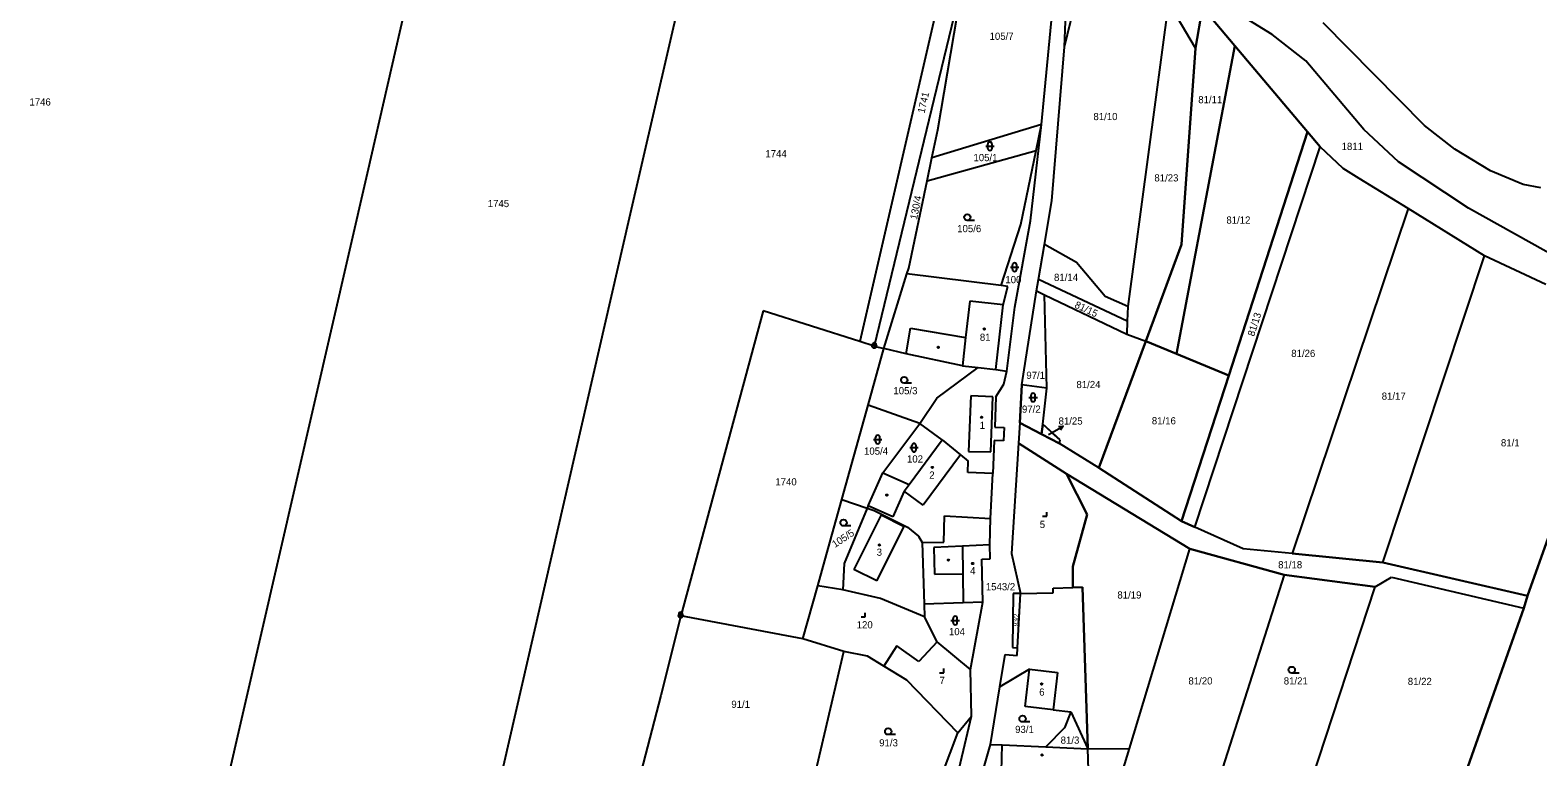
# Model space of a CAD drawing. Extents: x -801826 to -800592, y -1032871 to -1031813.
# Drawn here: x -801815 to -801458.2, y -1032222.7 to -1032050.6 of the extents above; entities that cross this region are included whole.
import ezdxf

# ---------------------------------------------------------------- set-up
doc = ezdxf.new("R2010")
doc.units = 0
for name, color, linetype in [('Vrstva 1', 7, 'Continuous'), ('Vrstva 16', 7, 'Continuous'), ('Vrstva 18', 7, 'Continuous'), ('Vrstva 19', 7, 'Continuous'), ('Vrstva 24', 7, 'Continuous'), ('Vrstva 25', 7, 'Continuous'), ('Vrstva 4', 7, 'Continuous')]:
    doc.layers.add(name, color=color, linetype=linetype)

msp = doc.modelspace()

# ---------------------------------------------------------------- linework, layer by layer
at = {"layer": 'Vrstva 1'}
for p, q in [((-801696.39, -1031915.49), (-801735.27, -1032084.52)), ((-801635.15, -1031929.7), (-801673.2, -1032095.09)), ((-801592.85, -1032012.2), (-801618.6, -1032124.34)), ((-801570.22, -1032054.57), (-801564.72, -1032031.99)), ((-801593.88, -1032036.96), (-801615.22, -1032125.41)), ((-801600.19, -1032074.16), (-801593.88, -1032036.96)), ((-801575.66, -1032072.95), (-801571.93, -1032034.16)), ((-801570.22, -1032054.57), (-801569.48, -1032037.37)), ((-801545.6, -1032044.06), (-801555.21, -1032116.05)), ((-801539.15, -1032054.89), (-801545.6, -1032044.06)), ((-801539.15, -1032054.89), (-801537.52, -1032045.21)), ((-801537.52, -1032045.21), (-801539.15, -1032054.89)), ((-801537.52, -1032045.21), (-801529.87, -1032054.28)), ((-801529.87, -1032054.28), (-801537.52, -1032045.21)), ((-801521.04, -1032051.65), (-801529.66, -1032046.3)), ((-801484.98, -1032073.21), (-801508.93, -1032048.86)), ((-801573.2, -1032091.04), (-801570.22, -1032054.57)), ((-801543.66, -1032127.26), (-801529.87, -1032054.28)), ((-801543.66, -1032127.26), (-801529.87, -1032054.28)), ((-801529.87, -1032054.28), (-801543.66, -1032127.26)), ((-801542.47, -1032101.33), (-801539.15, -1032054.89)), ((-801539.15, -1032054.89), (-801542.47, -1032101.33)), ((-801529.87, -1032054.28), (-801512.68, -1032074.66)), ((-801512.68, -1032074.66), (-801529.87, -1032054.28)), ((-801513.04, -1032057.88), (-801521.04, -1032051.65)), ((-801499.37, -1032074.08), (-801513.04, -1032057.88)), ((-801575.66, -1032072.95), (-801601.58, -1032080.79)), ((-801601.58, -1032080.79), (-801600.19, -1032074.16)), ((-801578.22, -1032095.71), (-801575.66, -1032072.95)), ((-801576.93, -1032079.13), (-801575.66, -1032072.95)), ((-801531.32, -1032132.37), (-801512.68, -1032074.66)), ((-801531.32, -1032132.37), (-801512.68, -1032074.66)), ((-801512.68, -1032074.66), (-801531.32, -1032132.37)), ((-801512.68, -1032074.66), (-801509.66, -1032078.24)), ((-801509.66, -1032078.24), (-801512.68, -1032074.66)), ((-801491.14, -1032081.75), (-801499.37, -1032074.08)), ((-801477.81, -1032078.75), (-801484.98, -1032073.21)), ((-801602.73, -1032086.28), (-801576.93, -1032079.13)), ((-801580.52, -1032096.58), (-801576.93, -1032079.13)), ((-801539.33, -1032168.25), (-801509.66, -1032078.24)), ((-801539.33, -1032168.25), (-801509.66, -1032078.24)), ((-801504.27, -1032083.33), (-801509.66, -1032078.24)), ((-801469.34, -1032083.91), (-801477.81, -1032078.75)), ((-801602.73, -1032086.28), (-801601.58, -1032080.79)), ((-801500.48, -1032085.74), (-801504.27, -1032083.33)), ((-801474.57, -1032092.78), (-801491.14, -1032081.75)), ((-801735.27, -1032084.52), (-801774.16, -1032253.56)), ((-801607.05, -1032106.95), (-801602.73, -1032086.28)), ((-801488.81, -1032092.82), (-801500.48, -1032085.74)), ((-801461.63, -1032087.11), (-801469.34, -1032083.91)), ((-801457.47, -1032087.94), (-801461.63, -1032087.11)), ((-801574.95, -1032101.34), (-801573.2, -1032091.04)), ((-801488.81, -1032092.82), (-801516.29, -1032174.51)), ((-801488.81, -1032092.82), (-801516.29, -1032174.51)), ((-801470.82, -1032104.06), (-801488.81, -1032092.82)), ((-801470.82, -1032104.06), (-801488.81, -1032092.82)), ((-801452.83, -1032104.89), (-801474.57, -1032092.78)), ((-801673.2, -1032095.09), (-801711.24, -1032260.47)), ((-801585.14, -1032111.09), (-801580.52, -1032096.58)), ((-801581.96, -1032116.17), (-801578.22, -1032095.71)), ((-801576.36, -1032109.6), (-801574.95, -1032101.34)), ((-801567.33, -1032105.58), (-801574.95, -1032101.34)), ((-801550.96, -1032124.23), (-801542.47, -1032101.33)), ((-801542.47, -1032101.33), (-801550.96, -1032124.23)), ((-801494.86, -1032176.63), (-801470.82, -1032104.06)), ((-801494.86, -1032176.63), (-801470.82, -1032104.06)), ((-801456.3, -1032110.81), (-801470.82, -1032104.06)), ((-801612.91, -1032125.95), (-801607.47, -1032108.32)), ((-801607.47, -1032108.32), (-801607.05, -1032106.95)), ((-801585.14, -1032111.09), (-801607.47, -1032108.32)), ((-801560.57, -1032113.65), (-801567.33, -1032105.58)), ((-801583.58, -1032111.28), (-801585.14, -1032111.09)), ((-801584.71, -1032115.66), (-801583.58, -1032111.28)), ((-801576.83, -1032112.35), (-801576.36, -1032109.6)), ((-801555.35, -1032119.53), (-801576.36, -1032109.6)), ((-801580.28, -1032134.57), (-801576.83, -1032112.35)), ((-801576.83, -1032112.35), (-801574.91, -1032113.27)), ((-801574.91, -1032113.27), (-801555.47, -1032122.58)), ((-801574.33, -1032135.39), (-801574.91, -1032113.27)), ((-801555.21, -1032116.05), (-801560.57, -1032113.65)), ((-801641.49, -1032117.07), (-801661.01, -1032189.25)), ((-801618.6, -1032124.34), (-801641.49, -1032117.07)), ((-801586.44, -1032130.95), (-801584.71, -1032115.66)), ((-801583.86, -1032131.32), (-801581.96, -1032116.17)), ((-801555.21, -1032116.05), (-801555.35, -1032119.53)), ((-801555.35, -1032119.53), (-801555.47, -1032122.58)), ((-801555.47, -1032122.58), (-801550.96, -1032124.23)), ((-801460.58, -1032184.52), (-801438.33, -1032121.65)), ((-801438.33, -1032121.65), (-801460.58, -1032184.52)), ((-801615.22, -1032125.41), (-801618.6, -1032124.34)), ((-801616.66, -1032139.4), (-801612.91, -1032125.95)), ((-801615.22, -1032125.41), (-801612.91, -1032125.95)), ((-801607.7, -1032127.27), (-801612.91, -1032125.95)), ((-801562.08, -1032154.26), (-801550.96, -1032124.23)), ((-801550.96, -1032124.23), (-801562.08, -1032154.26)), ((-801550.96, -1032124.23), (-801543.66, -1032127.26)), ((-801550.96, -1032124.23), (-801543.66, -1032127.26)), ((-801543.66, -1032127.26), (-801550.96, -1032124.23)), ((-801594.34, -1032130.06), (-801607.7, -1032127.27)), ((-801543.66, -1032127.26), (-801531.32, -1032132.37)), ((-801543.66, -1032127.26), (-801531.32, -1032132.37)), ((-801531.32, -1032132.37), (-801543.66, -1032127.26)), ((-801600.42, -1032137.74), (-801590.61, -1032130.48)), ((-801594.34, -1032130.06), (-801590.61, -1032130.48)), ((-801590.61, -1032130.48), (-801586.44, -1032130.95)), ((-801586.44, -1032130.95), (-801583.86, -1032131.32)), ((-801584.52, -1032134.38), (-801583.86, -1032131.32)), ((-801542.47, -1032166.88), (-801531.32, -1032132.37)), ((-801531.32, -1032132.37), (-801542.47, -1032166.88)), ((-801542.47, -1032166.88), (-801531.32, -1032132.37)), ((-801586.42, -1032137.42), (-801584.52, -1032134.38)), ((-801580.75, -1032143.57), (-801580.28, -1032134.57)), ((-801580.28, -1032134.57), (-801580.75, -1032143.57)), ((-801574.33, -1032135.39), (-801580.28, -1032134.57)), ((-801574.33, -1032135.39), (-801580.28, -1032134.57)), ((-801575.35, -1032143.86), (-801574.33, -1032135.39)), ((-801575.35, -1032143.86), (-801574.33, -1032135.39)), ((-801622.88, -1032161.7), (-801616.66, -1032139.4)), ((-801604.39, -1032143.72), (-801616.66, -1032139.4)), ((-801604.39, -1032143.72), (-801600.42, -1032137.74)), ((-801586.42, -1032137.42), (-801586.7, -1032144.58)), ((-801613.16, -1032155.4), (-801604.39, -1032143.72)), ((-801599.15, -1032147.62), (-801604.39, -1032143.72)), ((-801580.75, -1032143.57), (-801581.06, -1032148.37)), ((-801580.75, -1032143.57), (-801581.06, -1032148.37)), ((-801575.64, -1032146.25), (-801580.75, -1032143.57)), ((-801575.64, -1032146.25), (-801580.75, -1032143.57)), ((-801580.75, -1032143.57), (-801575.64, -1032146.25)), ((-801575.35, -1032143.86), (-801575.64, -1032146.25)), ((-801575.35, -1032143.86), (-801575.64, -1032146.25)), ((-801575.64, -1032146.25), (-801575.35, -1032143.86)), ((-801571.25, -1032147.62), (-801575.35, -1032143.86)), ((-801606.96, -1032158.17), (-801599.15, -1032147.62)), ((-801599.15, -1032147.62), (-801594.84, -1032151.14)), ((-801586.7, -1032144.58), (-801584.5, -1032144.66)), ((-801584.5, -1032144.66), (-801584.62, -1032147.83)), ((-801571.38, -1032148.48), (-801575.64, -1032146.25)), ((-801571.38, -1032148.48), (-801575.64, -1032146.25)), ((-801575.64, -1032146.25), (-801571.38, -1032148.48)), ((-801571.38, -1032148.48), (-801571.25, -1032147.62)), ((-801571.38, -1032148.48), (-801571.25, -1032147.62)), ((-801594.84, -1032151.14), (-801592.98, -1032152.66)), ((-801586.82, -1032147.74), (-801587.13, -1032155.6)), ((-801584.62, -1032147.83), (-801586.82, -1032147.74)), ((-801581.06, -1032148.37), (-801582.72, -1032174.51)), ((-801581.06, -1032148.37), (-801582.72, -1032174.51)), ((-801569.71, -1032155.65), (-801581.06, -1032148.37)), ((-801569.71, -1032155.65), (-801581.06, -1032148.37)), ((-801581.06, -1032148.37), (-801569.71, -1032155.65)), ((-801562.08, -1032154.26), (-801571.38, -1032148.48)), ((-801562.08, -1032154.26), (-801571.38, -1032148.48)), ((-801593.08, -1032155.37), (-801592.98, -1032152.66)), ((-801542.47, -1032166.88), (-801562.08, -1032154.26)), ((-801562.08, -1032154.26), (-801542.47, -1032166.88)), ((-801542.47, -1032166.88), (-801562.08, -1032154.26)), ((-801616.66, -1032163.25), (-801613.16, -1032155.4)), ((-801613.16, -1032155.4), (-801606.96, -1032158.17)), ((-801587.13, -1032155.6), (-801593.08, -1032155.37)), ((-801587.74, -1032166.2), (-801587.13, -1032155.6)), ((-801564.85, -1032165.28), (-801569.71, -1032155.65)), ((-801569.71, -1032155.65), (-801540.51, -1032173.41)), ((-801564.85, -1032165.28), (-801569.71, -1032155.65)), ((-801569.71, -1032155.65), (-801540.51, -1032173.41)), ((-801569.71, -1032155.65), (-801564.85, -1032165.28)), ((-801540.51, -1032173.41), (-801569.71, -1032155.65)), ((-801626.52, -1032174.73), (-801622.88, -1032161.7)), ((-801622.88, -1032161.7), (-801616.89, -1032163.75)), ((-801616.89, -1032163.75), (-801622.35, -1032176.9)), ((-801616.66, -1032163.25), (-801616.89, -1032163.75)), ((-801616.89, -1032163.75), (-801615.25, -1032164.31)), ((-801615.25, -1032164.31), (-801607.33, -1032168.28)), ((-801568.24, -1032177.58), (-801564.85, -1032165.28)), ((-801568.24, -1032177.58), (-801564.85, -1032165.28)), ((-801564.85, -1032165.28), (-801568.24, -1032177.58)), ((-801607.33, -1032168.28), (-801604.76, -1032170.44)), ((-801598.76, -1032171.83), (-801598.55, -1032165.58)), ((-801598.55, -1032165.58), (-801587.74, -1032166.2)), ((-801587.88, -1032172.45), (-801587.74, -1032166.2)), ((-801539.33, -1032168.25), (-801542.47, -1032166.88)), ((-801542.47, -1032166.88), (-801539.33, -1032168.25)), ((-801539.33, -1032168.25), (-801542.47, -1032166.88)), ((-801527.92, -1032173.38), (-801539.33, -1032168.25)), ((-801527.92, -1032173.38), (-801539.33, -1032168.25)), ((-801604.76, -1032170.44), (-801603.87, -1032171.87)), ((-801603.87, -1032171.87), (-801598.76, -1032171.83)), ((-801603.87, -1032171.87), (-801603.38, -1032186.52)), ((-801587.8, -1032175.74), (-801587.88, -1032172.45)), ((-801628.6, -1032182.17), (-801626.52, -1032174.73)), ((-801589.74, -1032175.82), (-801587.8, -1032175.74)), ((-801589.52, -1032186), (-801589.74, -1032175.82)), ((-801582.72, -1032174.51), (-801580.58, -1032183.95)), ((-801582.72, -1032174.51), (-801580.58, -1032183.95)), ((-801554.81, -1032220.67), (-801540.51, -1032173.41)), ((-801554.81, -1032220.67), (-801540.51, -1032173.41)), ((-801518.17, -1032179.53), (-801540.51, -1032173.41)), ((-801540.51, -1032173.41), (-801518.17, -1032179.53)), ((-801516.29, -1032174.51), (-801527.92, -1032173.38)), ((-801516.29, -1032174.51), (-801527.92, -1032173.38)), ((-801516.29, -1032174.51), (-801494.86, -1032176.63)), ((-801516.29, -1032174.51), (-801494.86, -1032176.63)), ((-801494.86, -1032176.63), (-801516.29, -1032174.51)), ((-801622.35, -1032176.9), (-801622.62, -1032183.14)), ((-801568.2, -1032182.56), (-801568.24, -1032177.58)), ((-801568.2, -1032182.56), (-801568.24, -1032177.58)), ((-801568.24, -1032177.58), (-801568.2, -1032182.56)), ((-801518.17, -1032179.53), (-801535.05, -1032232.41)), ((-801496.63, -1032182.4), (-801518.17, -1032179.53)), ((-801518.17, -1032179.53), (-801496.63, -1032182.4)), ((-801494.86, -1032176.63), (-801460.58, -1032184.52)), ((-801460.58, -1032184.52), (-801494.86, -1032176.63)), ((-801632.1, -1032194.71), (-801628.6, -1032182.17)), ((-801622.62, -1032183.14), (-801628.6, -1032182.17)), ((-801613.75, -1032185.19), (-801622.62, -1032183.14)), ((-801572.9, -1032182.72), (-801568.2, -1032182.56)), ((-801572.9, -1032182.72), (-801568.2, -1032182.56)), ((-801572.87, -1032183.8), (-801572.9, -1032182.72)), ((-801572.87, -1032183.8), (-801572.9, -1032182.72)), ((-801565.96, -1032182.51), (-801568.2, -1032182.56)), ((-801568.2, -1032182.56), (-801565.96, -1032182.51)), ((-801564.66, -1032220.77), (-801565.96, -1032182.51)), ((-801565.96, -1032182.51), (-801564.66, -1032220.77)), ((-801511.73, -1032228.35), (-801496.63, -1032182.4)), ((-801496.63, -1032182.4), (-801492.79, -1032180.13)), ((-801496.63, -1032182.4), (-801492.79, -1032180.13)), ((-801492.79, -1032180.13), (-801461.5, -1032187.46)), ((-801492.79, -1032180.13), (-801461.5, -1032187.46)), ((-801603.31, -1032189.54), (-801613.75, -1032185.19)), ((-801594.15, -1032186.18), (-801603.38, -1032186.52)), ((-801603.38, -1032186.52), (-801603.31, -1032189.54)), ((-801589.52, -1032186), (-801594.15, -1032186.18)), ((-801592.45, -1032201.97), (-801589.52, -1032186)), ((-801582.3, -1032183.98), (-801582.5, -1032196.8)), ((-801580.58, -1032183.95), (-801582.3, -1032183.98)), ((-801581.29, -1032196.85), (-801580.58, -1032183.95)), ((-801580.58, -1032183.95), (-801572.87, -1032183.8)), ((-801580.58, -1032183.95), (-801572.87, -1032183.8)), ((-801461.5, -1032187.46), (-801460.58, -1032184.52)), ((-801460.58, -1032184.52), (-801461.5, -1032187.46)), ((-801461.5, -1032187.46), (-801460.58, -1032184.52)), ((-801661.01, -1032189.25), (-801665.7, -1032208.11)), ((-801634.66, -1032194.23), (-801661.01, -1032189.25)), ((-801600.29, -1032195.45), (-801603.31, -1032189.54)), ((-801474.72, -1032225.02), (-801461.5, -1032187.46)), ((-801461.5, -1032187.46), (-801474.72, -1032225.02)), ((-801632.1, -1032194.71), (-801634.66, -1032194.23)), ((-801622.41, -1032197.71), (-801632.1, -1032194.71)), ((-801609.89, -1032196.36), (-801612.98, -1032201.16)), ((-801604.63, -1032200.11), (-801609.89, -1032196.36)), ((-801600.29, -1032195.45), (-801604.63, -1032200.11)), ((-801592.45, -1032201.97), (-801600.29, -1032195.45)), ((-801582.5, -1032196.8), (-801581.29, -1032196.85)), ((-801581.39, -1032198.64), (-801581.29, -1032196.85)), ((-801630.3, -1032231.27), (-801622.41, -1032197.71)), ((-801616.84, -1032198.81), (-801622.41, -1032197.71)), ((-801612.98, -1032201.16), (-801616.84, -1032198.81)), ((-801607.5, -1032204.51), (-801612.98, -1032201.16)), ((-801585.47, -1032206.05), (-801584.24, -1032198.44)), ((-801584.24, -1032198.44), (-801581.39, -1032198.64)), ((-801595.46, -1032216.99), (-801607.5, -1032204.51)), ((-801592.18, -1032213.05), (-801592.45, -1032201.97)), ((-801578.49, -1032201.93), (-801585.47, -1032206.05)), ((-801579.52, -1032210.71), (-801578.49, -1032201.93)), ((-801665.7, -1032208.11), (-801671.46, -1032230.29)), ((-801587.68, -1032219.71), (-801585.47, -1032206.05)), ((-801572.9, -1032211.49), (-801579.52, -1032210.71)), ((-801572.9, -1032211.49), (-801568.72, -1032211.97)), ((-801601.75, -1032253.31), (-801592.18, -1032213.05)), ((-801595.46, -1032216.99), (-801592.18, -1032213.05)), ((-801568.72, -1032211.97), (-801570.15, -1032215.77)), ((-801568.72, -1032211.97), (-801564.66, -1032220.77)), ((-801602.24, -1032235.1), (-801595.46, -1032216.99)), ((-801570.15, -1032215.77), (-801574.57, -1032220.31)), ((-801592.61, -1032236.62), (-801587.68, -1032219.71)), ((-801587.68, -1032219.71), (-801584.92, -1032219.84)), ((-801584.92, -1032219.84), (-801574.57, -1032220.31)), ((-801574.57, -1032220.31), (-801564.66, -1032220.77)), ((-801564.66, -1032220.77), (-801554.81, -1032220.67)), ((-801564.66, -1032220.77), (-801554.81, -1032220.67)), ((-801564.26, -1032232.36), (-801564.66, -1032220.77)), ((-801559.71, -1032236.89), (-801554.81, -1032220.67))]:
    msp.add_line(p, q, dxfattribs=at)
msp.add_lwpolyline([(-801571.25, -1032147.62), (-801573.17, -1032145.86), (-801575.35, -1032143.86)], dxfattribs=at)
at = {"layer": 'Vrstva 16'}
for p, q in [((-801573.96, -1032146.31), (-801573.13, -1032145.83)), ((-801573.13, -1032145.83), (-801570.52, -1032144.35))]:
    msp.add_line(p, q, dxfattribs=at)
msp.add_lwpolyline([(-801571.64, -1032144.41), (-801570.52, -1032144.35), (-801571.14, -1032145.28)], dxfattribs=at)
at = {"layer": 'Vrstva 24'}
for centre, radius in [((-801615.22, -1032125.41), 0.5), ((-801615.22, -1032125.41), 0.0364), ((-801661.01, -1032189.25), 0.5), ((-801661.01, -1032189.25), 0.0364)]:
    msp.add_circle(centre, radius, dxfattribs=at)
for centre in [(-801615.22, -1032125.04), (-801661.01, -1032188.88)]:
    msp.add_arc(centre, 0.45, 344.4473, 196.3778, dxfattribs=at)
at = {"layer": 'Vrstva 25'}
for p, q in [((-801588.84, -1032078.09), (-801586.84, -1032078.09)), ((-801588.34, -1032078.59), (-801588.34, -1032077.59)), ((-801587.34, -1032078.59), (-801587.34, -1032077.59)), ((-801591.45, -1032095.65), (-801593.2, -1032095.65)), ((-801583, -1032106.72), (-801581, -1032106.72)), ((-801582.5, -1032107.22), (-801582.5, -1032106.22)), ((-801581.5, -1032107.22), (-801581.5, -1032106.22)), ((-801606.37, -1032134.19), (-801608.12, -1032134.19)), ((-801578.61, -1032137.55), (-801576.61, -1032137.55)), ((-801578.11, -1032138.05), (-801578.11, -1032137.05)), ((-801577.11, -1032138.05), (-801577.11, -1032137.05)), ((-801615.39, -1032147.53), (-801613.39, -1032147.53)), ((-801614.89, -1032148.03), (-801614.89, -1032147.03)), ((-801613.89, -1032148.03), (-801613.89, -1032147.03)), ((-801606.81, -1032149.44), (-801604.81, -1032149.44)), ((-801606.31, -1032149.94), (-801606.31, -1032148.94)), ((-801605.31, -1032149.94), (-801605.31, -1032148.94)), ((-801574.38, -1032165.69), (-801574.38, -1032164.69)), ((-801620.73, -1032167.98), (-801622.48, -1032167.98)), ((-801575.38, -1032165.69), (-801574.38, -1032165.69)), ((-801618.35, -1032189.53), (-801617.35, -1032189.53)), ((-801617.35, -1032189.53), (-801617.35, -1032188.53)), ((-801597.06, -1032190.38), (-801595.06, -1032190.38)), ((-801596.56, -1032190.88), (-801596.56, -1032189.88)), ((-801595.56, -1032190.88), (-801595.56, -1032189.88)), ((-801599.76, -1032202.75), (-801598.76, -1032202.75)), ((-801598.76, -1032202.75), (-801598.76, -1032201.75)), ((-801514.65, -1032202.81), (-801516.4, -1032202.81)), ((-801578.36, -1032214.39), (-801580.11, -1032214.39)), ((-801610.17, -1032217.4), (-801611.92, -1032217.4))]:
    msp.add_line(p, q, dxfattribs=at)
for centre, radius in [((-801593.2, -1032094.9), 0.75), ((-801589.19, -1032121.37), 0.175), ((-801600.07, -1032125.7), 0.175), ((-801608.12, -1032133.44), 0.75), ((-801589.82, -1032142.25), 0.175), ((-801601.46, -1032154.13), 0.175), ((-801612.24, -1032160.68), 0.175), ((-801622.48, -1032167.23), 0.75), ((-801613.99, -1032172.49), 0.175), ((-801597.66, -1032176.07), 0.175), ((-801591.93, -1032176.88), 0.175), ((-801516.4, -1032202.06), 0.75), ((-801575.6, -1032205.42), 0.175), ((-801580.11, -1032213.64), 0.75), ((-801611.92, -1032216.65), 0.75), ((-801575.49, -1032222.21), 0.175)]:
    msp.add_circle(centre, radius, dxfattribs=at)
for centre, start, end in [((-801587.84, -1032077.59), 0, 180), ((-801587.84, -1032078.59), 180, 0), ((-801582, -1032106.22), 0, 180), ((-801582, -1032107.22), 180, 0), ((-801577.61, -1032137.05), 0, 180), ((-801577.61, -1032138.05), 180, 0), ((-801614.39, -1032147.03), 0, 180), ((-801614.39, -1032148.03), 180, 0), ((-801605.81, -1032148.94), 0, 180), ((-801605.81, -1032149.94), 180, 0), ((-801596.06, -1032189.88), 0, 180), ((-801596.06, -1032190.88), 180, 0)]:
    msp.add_arc(centre, 0.5, start, end, dxfattribs=at)
at = {"layer": 'Vrstva 4'}
for p, q in [((-801592.61, -1032114.76), (-801593.58, -1032123.36)), ((-801584.71, -1032115.66), (-801592.61, -1032114.76)), ((-801607.7, -1032127.27), (-801606.65, -1032121.13)), ((-801606.65, -1032121.13), (-801593.58, -1032123.36)), ((-801593.58, -1032123.36), (-801594.34, -1032130.06)), ((-801592.37, -1032137.18), (-801592.89, -1032150.35)), ((-801587.12, -1032137.39), (-801592.37, -1032137.18)), ((-801587.63, -1032150.44), (-801587.12, -1032137.39)), ((-801594.84, -1032151.14), (-801603.66, -1032163.06)), ((-801592.89, -1032150.35), (-801587.63, -1032150.44)), ((-801608.13, -1032159.75), (-801606.96, -1032158.17)), ((-801608.13, -1032159.75), (-801610.84, -1032165.84)), ((-801603.66, -1032163.06), (-801608.13, -1032159.75)), ((-801613.6, -1032165.37), (-801620.04, -1032178.32)), ((-801610.84, -1032165.84), (-801616.66, -1032163.25)), ((-801613.6, -1032165.37), (-801608.15, -1032168.08)), ((-801614.57, -1032180.98), (-801608.15, -1032168.08)), ((-801587.88, -1032172.45), (-801594.36, -1032172.75)), ((-801594.36, -1032172.75), (-801601.09, -1032173.06)), ((-801601.09, -1032173.06), (-801600.93, -1032179.42)), ((-801594.36, -1032172.75), (-801594.26, -1032179.35)), ((-801614.57, -1032180.98), (-801620.04, -1032178.32)), ((-801600.93, -1032179.42), (-801594.26, -1032179.35)), ((-801594.26, -1032179.35), (-801594.15, -1032186.18)), ((-801578.49, -1032201.93), (-801571.87, -1032202.71)), ((-801571.87, -1032202.71), (-801572.9, -1032211.49)), ((-801585.09, -1032226.1), (-801584.92, -1032219.84))]:
    msp.add_line(p, q, dxfattribs=at)

# ---------------------------------------------------------------- texts
at = {"layer": 'Vrstva 16'}
msp.add_text('81/25', height=1.7, dxfattribs=at).set_placement((-801571.59, -1032143.99))
at = {"layer": 'Vrstva 18'}
for s, height, p in [('105/7', 1.7, (-801587.92, -1032052.89)), ('1746', 1.7, (-801815.17, -1032068.45)), ('81/11', 1.7, (-801538.53, -1032067.9)), ('81/10', 1.7, (-801563.34, -1032071.9)), ('1744', 1.7, (-801640.99, -1032080.7)), ('105/1', 1.7, (-801591.74, -1032081.62)), ('1811', 1.7, (-801504.6, -1032078.97)), ('81/23', 1.7, (-801548.91, -1032086.42)), ('1745', 1.7, (-801706.69, -1032092.5)), ('105/6', 1.7, (-801595.58, -1032098.43)), ('81/12', 1.7, (-801531.87, -1032096.41)), ('81/14', 1.7, (-801572.67, -1032109.98)), ('100', 1.7, (-801584.18, -1032110.52)), ('81/26', 1.7, (-801516.52, -1032127.98)), ('97/1', 1.7, (-801579.22, -1032133.17)), ('105/3', 1.7, (-801610.68, -1032136.81)), ('81/24', 1.7, (-801567.36, -1032135.35)), ('81/17', 1.7, (-801495.11, -1032138.1)), ('97/2', 1.7, (-801580.25, -1032141.17)), ('81/16', 1.7, (-801549.52, -1032143.93)), ('81/25', 0.1, (-801574.13, -1032146.31)), ('81/1', 1.7, (-801466.9, -1032149.15)), ('105/4', 1.7, (-801617.63, -1032151.11)), ('102', 1.7, (-801607.47, -1032152.97)), ('1740', 1.7, (-801638.63, -1032158.39)), ('81/18', 1.7, (-801519.62, -1032178.02)), ('1543/2', 1.7, (-801588.81, -1032183.22)), ('81/19', 1.7, (-801557.67, -1032185.18)), ('104', 1.7, (-801597.54, -1032193.85)), ('81/20', 1.7, (-801540.85, -1032205.52)), ('81/21', 1.7, (-801518.29, -1032205.52)), ('81/22', 1.7, (-801488.94, -1032205.64)), ('91/1', 1.7, (-801649.04, -1032211.06)), ('93/1', 1.7, (-801581.88, -1032217)), ('91/3', 1.7, (-801614.04, -1032220.18)), ('81/3', 1.7, (-801571.1, -1032219.55))]:
    msp.add_text(s, height=height, dxfattribs=at).set_placement(p)
for s, height, rotation, p in [('1741', 1.7, 76.891, (-801603.33, -1032070.39)), ('130/4', 1.7, 78.7696, (-801605.1, -1032095.55)), ('81/15', 1.7, 334.7553, (-801567.95, -1032116.21)), ('81/13', 1.7, 72.419, (-801525.31, -1032123.21)), ('105/5', 1.7, 33.6198, (-801624.51, -1032173.22)), ('93/2', 1.14, 88.1298, (-801581.17, -1032191.8))]:
    msp.add_text(s, height=height, rotation=rotation, dxfattribs=at).set_placement(p)
at = {"layer": 'Vrstva 19'}
for s, p in [('81', (-801590.22, -1032124.15)), ('1', (-801590.26, -1032145.01)), ('2', (-801602.19, -1032156.79)), ('5', (-801576.04, -1032168.47)), ('3', (-801614.65, -1032175.05)), ('4', (-801592.52, -1032179.42)), ('120', (-801619.37, -1032192.24)), ('7', (-801599.76, -1032205.39)), ('6', (-801576.17, -1032208.16))]:
    msp.add_text(s, height=1.7, dxfattribs=at).set_placement(p)

doc.saveas('drawing.dxf')
